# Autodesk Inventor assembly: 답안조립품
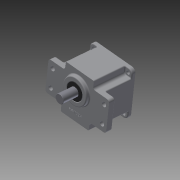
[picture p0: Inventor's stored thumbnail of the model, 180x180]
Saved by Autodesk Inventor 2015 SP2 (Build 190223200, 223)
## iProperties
Created: 2015-06
Part Number: 답안조립품
Document SubType Name: Assembly
Designer: AMC
Author: AMC
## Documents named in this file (11)
- C:\Users\AMC\Desktop\450620V1004\답안조립품.iam
- C:\Users\AMC\Desktop\450620V1004\본체.ipt
- C:\Users\AMC\Desktop\450620V1004\오일실 17x32x8.ipt
- C:\Users\AMC\Desktop\450620V1004\베어링 6003.ipt
- 베어링 6003.ipt
- C:\Users\AMC\Desktop\450620V1004\베어링 608.ipt
- 베어링 608.ipt
- C:\Users\AMC\Desktop\450620V1004\서브축.ipt
- C:\Users\AMC\Desktop\450620V1004\메인축.ipt
- C:\Users\AMC\Desktop\450620V1004\커버.ipt
- C:\Users\AMC\Desktop\450620V1004\M4x0.5x16.ipt
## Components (4 placed, 1 different names)
1. M4x0.5x12:1
2. M4x0.5x12:2
3. M4x0.5x12:3
4. M4x0.5x12:4
